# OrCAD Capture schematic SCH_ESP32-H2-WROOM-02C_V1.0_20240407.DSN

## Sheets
1 01_Design Block: title: <ESP32-H2-WROOM-02C>; rev: V1.0; note: <01_DesignBlock>
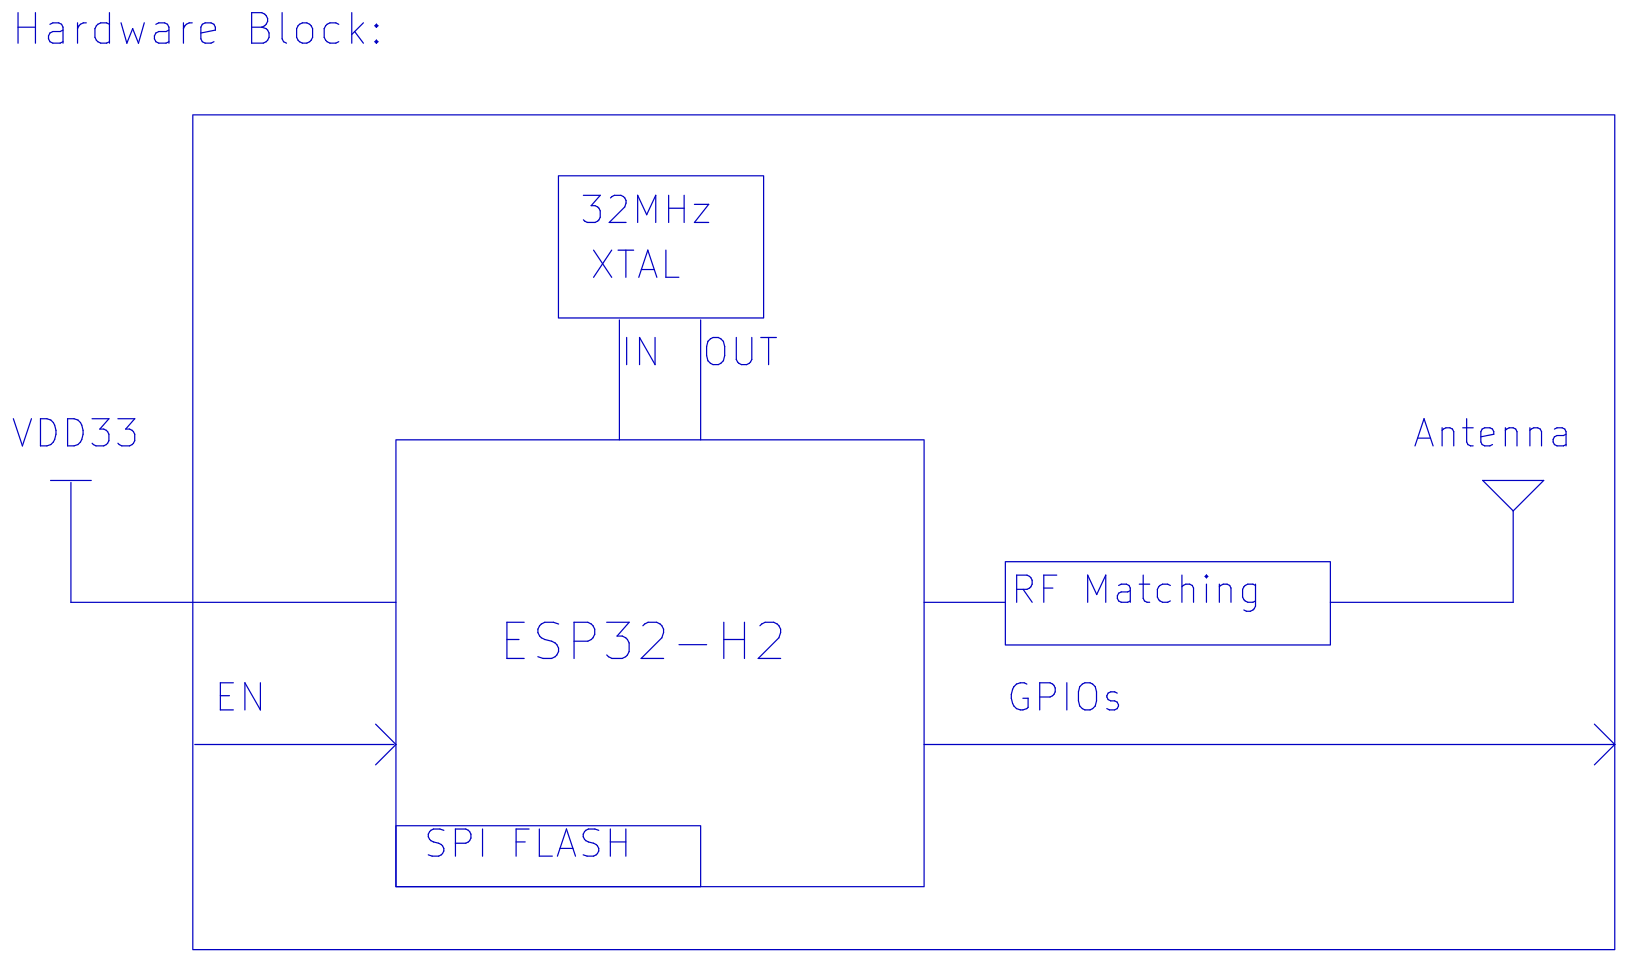
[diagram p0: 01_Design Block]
2 02_ ESP32-H2-WROOM-02C: size A4; note: <02_ESP32-H2-WROOM-02C>
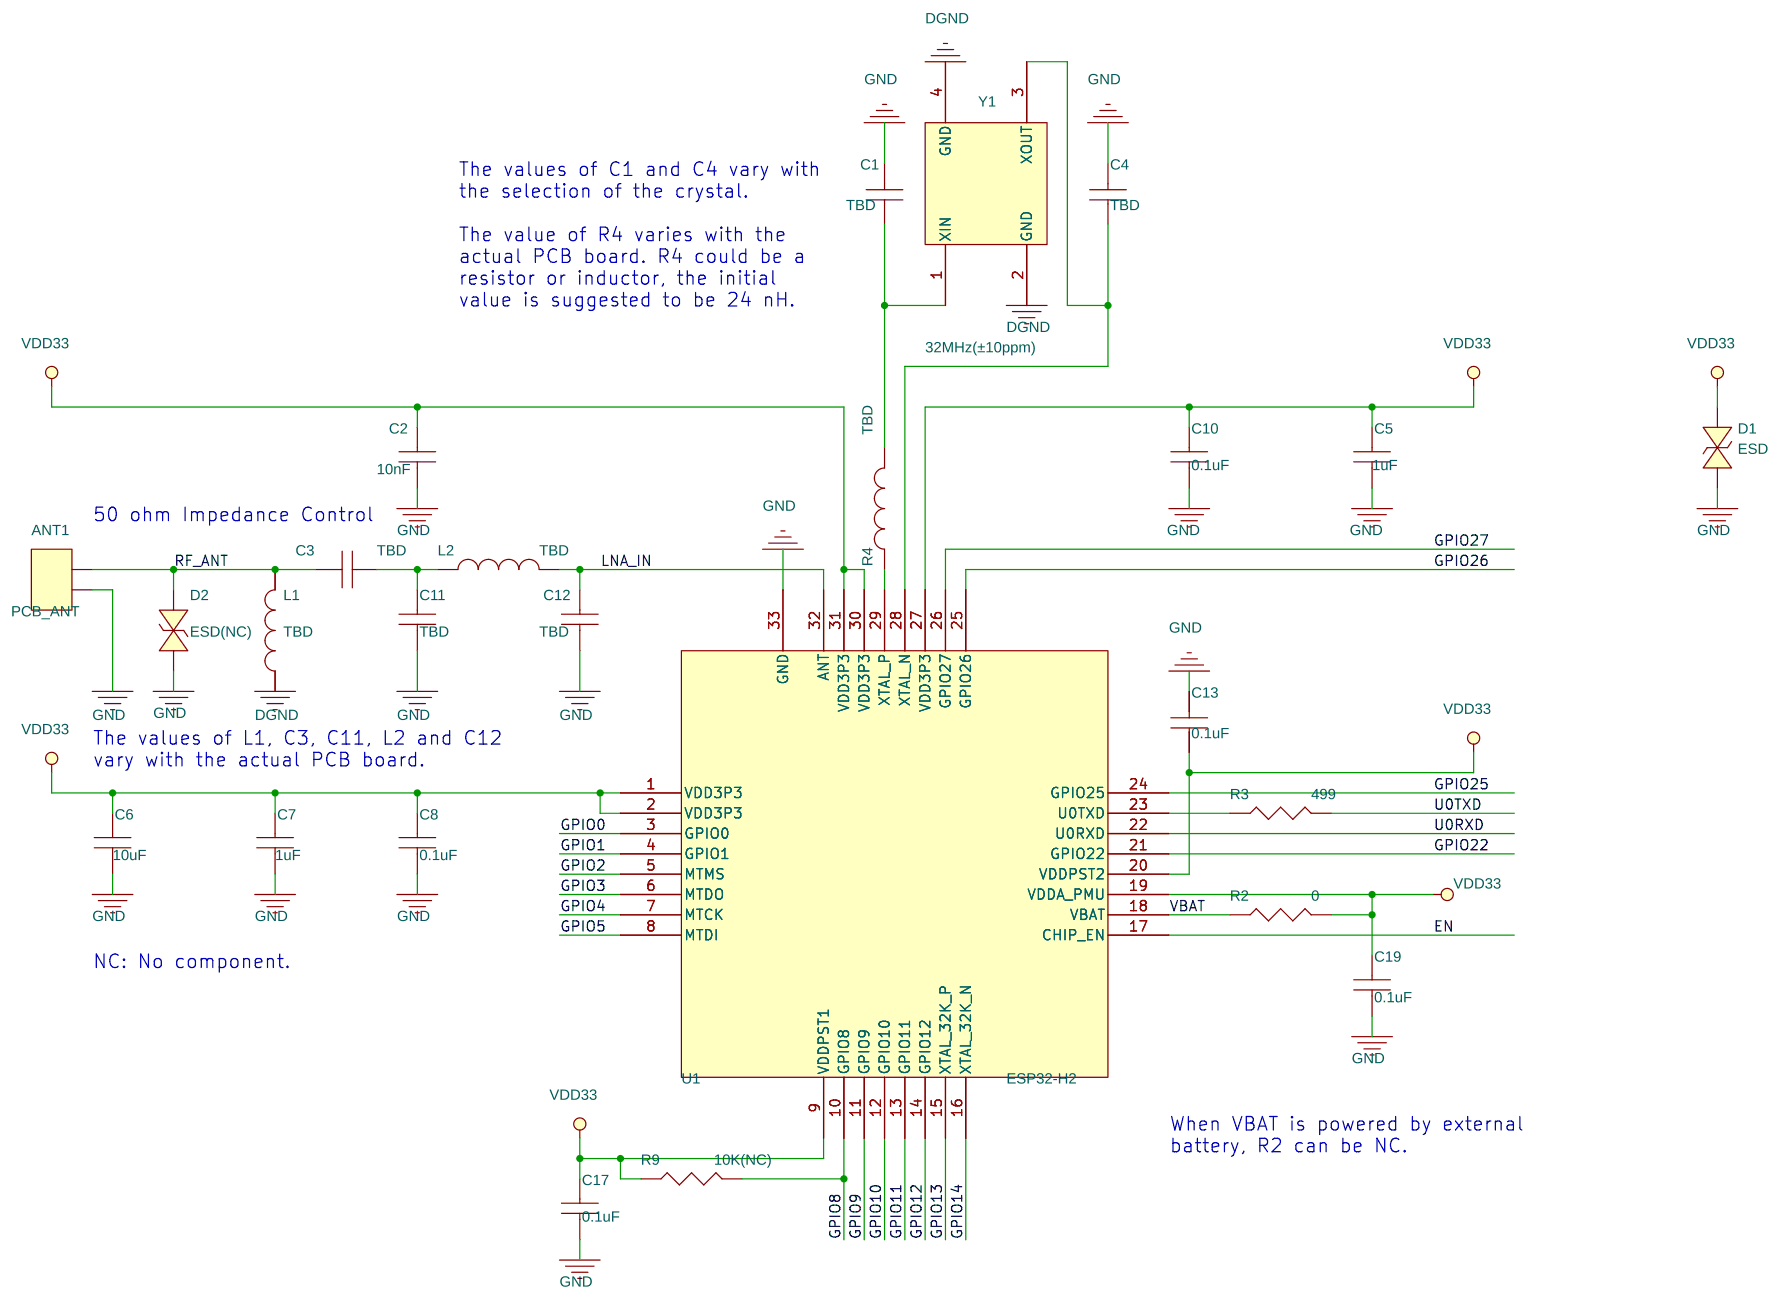
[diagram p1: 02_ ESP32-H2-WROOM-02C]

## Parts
ANT1  PCB_ANT  [MINI-ANT-TYPEB]
C1  TBD  [C0201]
C2  10nF  [C0201]
C3  TBD  [C0201]
C4  TBD  [C0201]
C5  1uF  [C0201]
C6  10uF  [C0402]
C7  1uF  [C0201]
C8  0.1uF  [C0201]
C10  0.1uF  [C0201]
C11  TBD  [C0201]
C12  TBD  [C0201]
C13  0.1uF  [C0201]
C17  0.1uF  [C0201]
C19  0.1uF  [C0201]
D1  ESD  [SOD882]
D2  ESD(NC)  [DFN0603]
L1  TBD  [L0201]
L2  TBD  [L0201]
R2  0  [R0201]
R3  499  [R0201]
R4  TBD  [R0201]
R9  10K(NC)  [R0201]
U1  ESP32-H2  [QFN32_0P4_4_E2P8]
Y1  32MHz(±10ppm)  [XTAL3225]

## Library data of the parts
ANT1 = PCB_ANT
C1 C3 C4 C11 C12 = CAPACITOR
C2 = CAPACITOR: CODE12: ES11.02.410.3.6.2.00; Part Number: ES11024103620000; Part Type: Capacitor
C5 C7 = CAPACITOR: CODE12: ES11.02.610.2.7.1.00; Part Number: ES11026102710000; Part Type: Capacitor
C6 = CAPACITOR: CODE12: ES11.04.710.2.7.1.00; Part Number: ES11047102710000; Part Type: Capacitor
C8 C10 C13 C17 C19 = CAPACITOR: CODE12: ES11.02.510.2.6.1.00; Part Number: ES11025102610000; Part Type: Capacitor
D1 = DIODE_BI_DIR: CODE12: ES31.32.0010.00.0.0; Part Number: ES31320010000001; Part Type: Diode
D2 = DIODE_BI_DIR: Options: ESD
L1 L2 R4 = INDUCTOR
R2 = RESISTOR: CODE12: ES21.02.0000.1.00.0; Part Number: ES21020000100002; Part Type: Resistor
R3 = RESISTOR: CODE12: ES21.02.2499.1.00.0; Part Number: ES21022499100002; Part Type: Resistor
R9 = RESISTOR: CODE12: ES21.02.4100.1.00.0; Part Number: ES21024100100002; Part Type: Resistor
U1 = ESP32-H2
Y1 = XTAL_4P

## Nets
GND: ANT1.2 C1.2 C2.2 C4.2 C5.2 C6.2 C7.2 C8.2 C10.2 C11.2 C12.2 C13.2 C17.2 C19.2 D1.2 D2.2 L1.2 U1.33(GND) Y1.2(GND) Y1.4(GND)
VBAT: R2.2 U1.18(VBAT)
VDD33: C2.1 C5.1 C6.1 C7.1 C8.1 C10.1 C13.1 C17.1 C19.1 D1.1 R2.1 R9.1 U1.1(VDD3P3) U1.2(VDD3P3) U1.9(VDDPST1) U1.19(VDDA_PMU) U1.20(VDDPST2) U1.27(VDD3P3) U1.30(VDD3P3) U1.31(VDD3P3)
EN: U1.17(CHIP_EN)
GPIO0: U1.3(GPIO0)
GPIO1: U1.4(GPIO1)
GPIO2: U1.5(MTMS)
GPIO3: U1.6(MTDO)
GPIO4: U1.7(MTCK)
GPIO5: U1.8(MTDI)
GPIO8: R9.2 U1.10(GPIO8)
GPIO9: U1.11(GPIO9)
GPIO10: U1.12(GPIO10)
GPIO11: U1.13(GPIO11)
GPIO12: U1.14(GPIO12)
GPIO13: U1.15(XTAL_32K_P)
GPIO14: U1.16(XTAL_32K_N)
GPIO22: U1.21(GPIO22)
GPIO25: U1.24(GPIO25)
GPIO26: U1.25(GPIO26)
GPIO27: U1.26(GPIO27)
LNA_IN: C12.1 L2.2 U1.32(ANT)
RF_ANT: ANT1.1 C3.2 D2.1 L1.1
U0RXD: U1.22(U0RXD)
U0TXD: R3.2
N16951109: C3.1 C11.1 L2.1
N17042307: R3.1 U1.23(U0TXD)
N17042571: C1.1 R4.1 Y1.1(XIN)
N17042573: R4.2 U1.29(XTAL_P)
N17042575: C4.1 U1.28(XTAL_N) Y1.3(XOUT)

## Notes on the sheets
sheet 1
- Hardware Block:
- 32MHz
- XTAL
- IN
- OUT
- VDD33
- Antenna
- RF Matching
- ESP32-H2
- EN
- GPIOs
- SPI FLASH
sheet 2
- The values of C1 and C4 vary with
  the selection of the crystal.
  The value of R4 varies with the
  actual PCB board. R4 could be a
  resistor or inductor, the initial
  value is suggested to be 24 nH.
- 50 ohm Impedance Control
- The values of L1, C3, C11, L2 and C12
  vary with the actual PCB board.
- NC: No component.
- When VBAT is powered by external
  battery, R2 can be NC.
